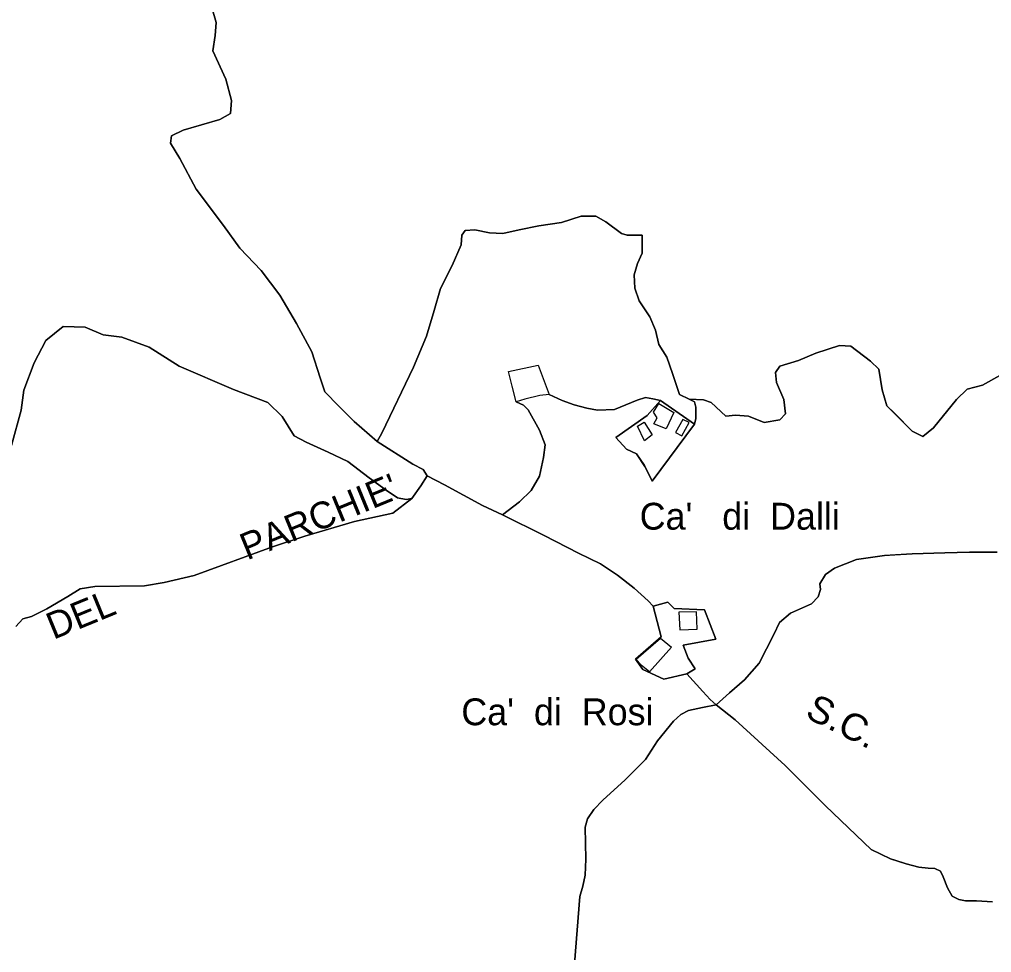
# Model space of a CAD drawing. Extents: x 645880 to 658994, y 884400 to 894744.
# Drawn here: x 653285 to 653901, y 891100 to 891691 of the extents above; entities that cross this region are included whole.
import ezdxf
from ezdxf.enums import TextEntityAlignment as Align

# ---------------------------------------------------------------- set-up
doc = ezdxf.new("R2010")
doc.units = 0
doc.header["$LTSCALE"] = 10
for name, color, linetype, lineweight in [('16', 7, 'Continuous', 25), ('18', 7, 'Continuous', 25), ('3', 7, 'Continuous', 25), ('4', 7, 'Continuous', 25)]:
    doc.layers.add(name, color=color, linetype=linetype, lineweight=lineweight)
doc.layers.add('60', color=7, linetype='Continuous')

msp = doc.modelspace()

# ---------------------------------------------------------------- linework, layer by layer
at = {"layer": '16'}
for points in [[(653982.6, 891577.12), (653973.26, 891579.64), (653963.41, 891578.13), (653958.74, 891573.6), (653953.56, 891554.48), (653953.56, 891524.3), (653953.04, 891499.64), (653949.93, 891489.58), (653943.19, 891484.55), (653929.78, 891480.64), (653921.48, 891475.61), (653906.44, 891465.54), (653895.55, 891459.51), (653885.7, 891456.99), (653878.96, 891450.45), (653864.44, 891432.34), (653857.7, 891426.8), (653850.96, 891430.32), (653839.8, 891441.5), (653839.8, 891441.51)], [(653712.85, 891434.77), (653713.65, 891438.39), (653713.86, 891445.39), (653712.99, 891448.89), (653709.6, 891450.58), (653703.38, 891453.57), (653698.9, 891466.76), (653695.38, 891477.12), (653690.2, 891485.17), (653688.12, 891494.22), (653684.49, 891502.78), (653677.75, 891512.84), (653675.16, 891520.89), (653674.64, 891529.44), (653676.72, 891536.49), (653679.83, 891543.03), (653679.83, 891554.6), (653670.17, 891554.46), (653666.54, 891555.47), (653656.69, 891563.02), (653650.46, 891566.54), (653641.13, 891566.54), (653628.68, 891562.51), (653614.16, 891560.5), (653601.72, 891557.98), (653591.35, 891555.47), (653583.05, 891555.97), (653573.72, 891557.98), (653567.49, 891557.48), (653565.42, 891554.46), (653564.9, 891548.42), (653559.2, 891535.34), (653551.94, 891520.75), (653547.79, 891506.66), (653543.12, 891490.56), (653534.82, 891470.94), (653514.63, 891428.94), (653511.76, 891423.65), (653534.38, 891409.3)], [(653282.78, 891306.52), (653287.22, 891311.4), (653292.53, 891312.73), (653302.29, 891317.61), (653315.58, 891325.59), (653323.56, 891330.47), (653332.87, 891331.8), (653364.34, 891332.24), (653376.75, 891334.46), (653395.81, 891338.9), (653445.45, 891357.08), (653465.84, 891363.73), (653497.31, 891373.04), (653521.69, 891378.36), (653533.65, 891387.68), (653530.21, 891386.92), (653524.55, 891388.08), (653517.52, 891392.8), (653506.71, 891400.67), (653493.19, 891411.16), (653480.76, 891416.93), (653466.7, 891423.22), (653459.13, 891427.42), (653451.57, 891439.48), (653442.38, 891448.4), (653420.75, 891456.79), (653386.15, 891471.47), (653367.23, 891483.53), (653349.93, 891489.83), (653338.03, 891491.4), (653326.68, 891496.12), (653312.62, 891496.64), (653301.81, 891487.73), (653294.24, 891473.57), (653287.75, 891456.26), (653286.13, 891443.68), (653279.91, 891421.22)], [(653839.8, 891441.51), (653834.88, 891446.43), (653831.77, 891456.49), (653829.69, 891469.57), (653824.51, 891474.6), (653812.06, 891484.16), (653804.8, 891484.66), (653789.76, 891479.63), (653778.87, 891475.1), (653766.95, 891471.58), (653764.35, 891467.56), (653764.87, 891461.02), (653769.54, 891450.45), (653770.53, 891441.37), (653766.95, 891437.37), (653757.09, 891435.86), (653747.24, 891439.88), (653738.94, 891440.39), (653732.72, 891439.88), (653723.39, 891448.44), (653718.55, 891450.08), (653709.6, 891450.58)], [(653554.39, 891396.26), (653578.51, 891383.22), (653591.21, 891377.35), (653601.97, 891385.5), (653609.46, 891392.68), (653614.68, 891401.81), (653617.29, 891413.55), (653618.26, 891421.7), (653614.63, 891430.96), (653607.51, 891443.87), (653604.58, 891446.81), (653599.78, 891448.86), (653597.29, 891458.87), (653594.95, 891468.17), (653613.91, 891472.07), (653620.83, 891453.6)], [(653691.31, 891449.65), (653686.47, 891450.84), (653681.86, 891451.64), (653676.66, 891449.84), (653662.24, 891444.03), (653651.43, 891443.63), (653644.63, 891444.83), (653636.62, 891447.04), (653629.01, 891449.64), (653620.83, 891453.6), (653614.83, 891452.8), (653605.42, 891450.6), (653599.78, 891448.86)], [(653620.83, 891453.6), (653629.01, 891449.64), (653636.62, 891447.04), (653644.63, 891444.83), (653651.43, 891443.63), (653662.24, 891444.03), (653676.66, 891449.84), (653681.86, 891451.64), (653686.47, 891450.84), (653691.31, 891449.65), (653712.85, 891434.77)], [(653709.6, 891450.58), (653712.99, 891448.89), (653713.86, 891445.39), (653713.65, 891438.39), (653712.85, 891434.77), (653686.09, 891398.67), (653681.46, 891407.83), (653676.19, 891415.97), (653669.89, 891418.97), (653662.98, 891426.33), (653683, 891440.16), (653691.31, 891449.65)], [(653599.78, 891448.86), (653604.58, 891446.81), (653607.51, 891443.87), (653614.63, 891430.96), (653618.26, 891421.7), (653617.29, 891413.55), (653614.68, 891401.81), (653609.46, 891392.68), (653601.97, 891385.5), (653591.21, 891377.35)], [(653534.38, 891409.3), (653540.91, 891405.97), (653543.41, 891402.07), (653554.39, 891396.26)], [(653591.21, 891377.35), (653578.51, 891383.22), (653554.39, 891396.26), (653543.41, 891402.07), (653539.38, 891395.54), (653533.65, 891387.68)], [(653533.65, 891387.68), (653521.69, 891378.36), (653497.31, 891373.04), (653465.84, 891363.73), (653445.45, 891357.08), (653395.81, 891338.9), (653376.75, 891334.46), (653364.34, 891332.24), (653332.87, 891331.8), (653323.56, 891330.47), (653315.58, 891325.59), (653302.29, 891317.61), (653292.53, 891312.73), (653287.22, 891311.4), (653282.78, 891306.52)], [(653686.64, 891319.48), (653683.63, 891322.8), (653674.69, 891330.89), (653664.06, 891338.98), (653653.42, 891346.22), (653639.38, 891353.03), (653617.67, 891364.1), (653591.21, 891377.35)], [(653591.21, 891377.35), (653617.67, 891364.1), (653639.38, 891353.03), (653653.42, 891346.22), (653664.06, 891338.98)], [(653718.1, 891265.32), (653722.78, 891260.21), (653726.72, 891256.83), (653735.02, 891264.44), (653744.53, 891272.79), (653753.87, 891283.36), (653763.2, 891301.47), (653766.83, 891309.02), (653773.67, 891314.84), (653781.45, 891318.36), (653787.15, 891320.88), (653791.3, 891325.4), (653792.86, 891329.93), (653792.34, 891333.45), (653795.97, 891339.49), (653801.67, 891343.52), (653815.68, 891349.05), (653833.31, 891351.57), (653839.8, 891351.94), (653850.94, 891352.57), (653871.68, 891353.08), (653887.24, 891353.58), (653904.87, 891353.58)], [(653664.06, 891338.98), (653674.69, 891330.89), (653683.63, 891322.8), (653686.64, 891319.48)], [(653686.64, 891319.48), (653696.05, 891321.84), (653699.96, 891317.92), (653719.18, 891317.1), (653726.35, 891298.57), (653705.69, 891294.67), (653708.89, 891286.43), (653713.3, 891279.66), (653707.96, 891276.59), (653718.1, 891265.32)], [(653726.72, 891256.83), (653722.78, 891260.21), (653718.1, 891265.32), (653707.96, 891276.59), (653693.57, 891273.16), (653680.08, 891279.34), (653675.41, 891285.76), (653691.87, 891299.88), (653686.64, 891319.48)], [(653619.68, 891027.76), (653624.41, 891037.97), (653629.84, 891059.69), (653633.37, 891070.27), (653636.89, 891092.8), (653640.15, 891135.42), (653642.05, 891141.93), (653643.67, 891148.99), (653643.95, 891159.03), (653643.67, 891179.39), (653645.03, 891184.55), (653649.1, 891190.52), (653654.8, 891196.49), (653668.91, 891209.25), (653681.93, 891222.28), (653689.52, 891233.95), (653699.56, 891246.44), (653704.17, 891250.78), (653709.06, 891253.23), (653718.01, 891255.13), (653726.72, 891256.83)], [(653726.72, 891256.83), (653718.01, 891255.13), (653709.06, 891253.23), (653704.17, 891250.78), (653699.56, 891246.44), (653689.52, 891233.95), (653681.93, 891222.28), (653668.91, 891209.25), (653654.8, 891196.49), (653649.1, 891190.52), (653645.03, 891184.55), (653643.67, 891179.39), (653643.95, 891159.03), (653643.67, 891148.99), (653642.05, 891141.93), (653640.15, 891135.42), (653636.89, 891092.8), (653633.37, 891070.27), (653629.84, 891059.69), (653624.41, 891037.97), (653619.68, 891027.76), (653636.37, 891015.55)], [(653839.8, 891158.4), (653837.14, 891159.19), (653824.83, 891165.18), (653795.91, 891192.82), (653770.28, 891218.48), (653738.73, 891247.44), (653726.72, 891256.83)], [(653901.81, 891131.94), (653891.76, 891132.69), (653884.8, 891132.69), (653880.42, 891133.44), (653876.3, 891135.69), (653873.21, 891140.94), (653870.63, 891147.94), (653868.83, 891151.44), (653865.22, 891153.19), (653861.1, 891153.44), (653855.18, 891153.94), (653847.19, 891156.19), (653839.8, 891158.4)]]:
    msp.add_lwpolyline(points, dxfattribs=at)
at = {"layer": '18'}
for points in [[(653511.76, 891423.65), (653497.21, 891436.44), (653487.5, 891446.16), (653478.53, 891455.13), (653475.54, 891464.1), (653470.31, 891480.55), (653460.6, 891498.5), (653450.14, 891516.44), (653438.18, 891532.15), (653424.73, 891546.35), (653414.27, 891560.56), (653397.09, 891583.74), (653386.63, 891603.18), (653380.65, 891612.9), (653381.4, 891617.39), (653388.87, 891621.12), (653412.03, 891627.85), (653418.76, 891631.59), (653419.5, 891639.82), (653415.77, 891653.28), (653407.55, 891671.22), (653409.04, 891680.94), (653409.79, 891689.17), (653407.03, 891698.75)], [(653407.03, 891698.75), (653409.79, 891689.17), (653409.04, 891680.94), (653407.55, 891671.22), (653415.77, 891653.28), (653419.5, 891639.82), (653418.76, 891631.59), (653412.03, 891627.85), (653388.87, 891621.12), (653381.4, 891617.39), (653380.65, 891612.9), (653386.63, 891603.18), (653397.09, 891583.74), (653414.27, 891560.56), (653424.73, 891546.35), (653438.18, 891532.15), (653450.14, 891516.44), (653460.6, 891498.5), (653470.31, 891480.55), (653475.54, 891464.1), (653478.53, 891455.13), (653487.5, 891446.16), (653497.21, 891436.44), (653511.76, 891423.65), (653514.63, 891428.94), (653534.82, 891470.94), (653543.12, 891490.56), (653547.79, 891506.66), (653551.94, 891520.75), (653559.2, 891535.34), (653564.9, 891548.42), (653565.42, 891554.46), (653567.49, 891557.48), (653573.72, 891557.98), (653583.05, 891555.97), (653591.35, 891555.47), (653601.72, 891557.98), (653614.16, 891560.5), (653628.68, 891562.51), (653641.13, 891566.54)], [(653641.13, 891566.54), (653650.46, 891566.54), (653656.69, 891563.02), (653666.54, 891555.47), (653670.17, 891554.46), (653679.83, 891554.6), (653679.83, 891543.03), (653676.72, 891536.49), (653674.64, 891529.44), (653675.16, 891520.89), (653677.75, 891512.84), (653684.49, 891502.78), (653688.12, 891494.22), (653690.2, 891485.17), (653695.38, 891477.12), (653698.9, 891466.76), (653703.38, 891453.57), (653709.6, 891450.58), (653718.55, 891450.08), (653723.39, 891448.44), (653732.72, 891439.88), (653738.94, 891440.39), (653747.24, 891439.88), (653757.09, 891435.86), (653766.95, 891437.37), (653770.53, 891441.37), (653769.54, 891450.45), (653764.87, 891461.02), (653764.35, 891467.56), (653766.95, 891471.58), (653778.87, 891475.1), (653789.76, 891479.63), (653804.8, 891484.66), (653812.06, 891484.16), (653824.51, 891474.6), (653829.69, 891469.57), (653831.77, 891456.49), (653834.88, 891446.43), (653850.96, 891430.32), (653857.7, 891426.8)], [(653279.91, 891421.22), (653286.13, 891443.68), (653287.75, 891456.26), (653294.24, 891473.57), (653301.81, 891487.73), (653312.62, 891496.64), (653326.68, 891496.12), (653338.03, 891491.4), (653349.93, 891489.83), (653367.23, 891483.53), (653386.15, 891471.47), (653420.75, 891456.79), (653442.38, 891448.4), (653451.57, 891439.48), (653459.13, 891427.42)], [(653857.7, 891426.8), (653864.44, 891432.34), (653878.96, 891450.45), (653885.7, 891456.99), (653895.55, 891459.51), (653906.44, 891465.54)], [(653459.13, 891427.42), (653466.7, 891423.22), (653480.76, 891416.93), (653493.19, 891411.16), (653506.71, 891400.67), (653517.52, 891392.8), (653524.55, 891388.08), (653530.21, 891386.93), (653533.65, 891387.68), (653539.37, 891395.54), (653543.4, 891402.08), (653540.9, 891405.97), (653534.37, 891409.3), (653511.76, 891423.65)], [(653904.87, 891353.58), (653887.24, 891353.58), (653871.68, 891353.08), (653850.94, 891352.57), (653833.31, 891351.57), (653815.68, 891349.05), (653801.67, 891343.52)], [(653801.67, 891343.52), (653795.97, 891339.49), (653792.34, 891333.45), (653792.86, 891329.93), (653791.3, 891325.4), (653787.15, 891320.88), (653781.45, 891318.36), (653773.67, 891314.84), (653766.83, 891309.02), (653763.2, 891301.47), (653753.87, 891283.36), (653744.53, 891272.79), (653735.02, 891264.44), (653726.72, 891256.83), (653738.73, 891247.44), (653770.28, 891218.48), (653795.91, 891192.82), (653824.83, 891165.18), (653837.14, 891159.19), (653847.19, 891156.19), (653855.18, 891153.94), (653861.1, 891153.44), (653865.22, 891153.19), (653868.83, 891151.44), (653870.63, 891147.94), (653873.21, 891140.94), (653876.3, 891135.69), (653880.42, 891133.44), (653884.8, 891132.69), (653891.76, 891132.69), (653901.81, 891131.94)]]:
    msp.add_lwpolyline(points, dxfattribs=at)
at = {"layer": '3'}
for points in [[(653699.96, 891317.92), (653696.05, 891321.84), (653686.64, 891319.48)], [(653686.64, 891319.48), (653691.87, 891299.88), (653675.41, 891285.76), (653680.08, 891279.34), (653693.57, 891273.16), (653707.96, 891276.59), (653713.3, 891279.66), (653708.89, 891286.43), (653705.69, 891294.67), (653726.35, 891298.57), (653719.18, 891317.1), (653699.96, 891317.92)]]:
    msp.add_lwpolyline(points, dxfattribs=at)
for points in [[(653703.01, 891315.59), (653703.62, 891304.39), (653714.6, 891304.9), (653714.08, 891315.81)], [(653691.35, 891299.09), (653698.4, 891293.34), (653684.33, 891277.77), (653679.01, 891282.06), (653676.02, 891285.83)]]:
    msp.add_lwpolyline(points, close=True, dxfattribs=at)
at = {"layer": '4'}
for points in [[(653605.42, 891450.6), (653599.78, 891448.86), (653597.29, 891458.87), (653594.95, 891468.17), (653613.91, 891472.07), (653620.83, 891453.6), (653614.83, 891452.8)], [(653676.19, 891415.97), (653681.28, 891408.6), (653686.09, 891398.67), (653712.85, 891434.77), (653691.31, 891449.65), (653683, 891440.16), (653662.98, 891426.33), (653669.89, 891418.97)], [(653686.87, 891442.38), (653690.26, 891447.89), (653699.74, 891442.15), (653694.94, 891431.72), (653687.22, 891434.88), (653689.21, 891438.63)], [(653705.48, 891437.7), (653700.91, 891429.5), (653704.78, 891427.39), (653709.46, 891435.82)], [(653681.01, 891435.94), (653686.05, 891427.86), (653681.13, 891424.22), (653676.68, 891433.36)]]:
    msp.add_lwpolyline(points, close=True, dxfattribs=at)

# ---------------------------------------------------------------- texts
at = {"layer": '60'}
msp.add_text("S.C.            DEL              PARCHIE'", height=17, rotation=22.275, dxfattribs=at).set_placement((653361.15, 891320.37), align=Align.CENTER)
for s, p in [("Ca'   di  Dalli", (653741.6, 891367.88)), ("Ca'  di  Rosi", (653626.01, 891243.93))]:
    msp.add_text(s, height=17, dxfattribs=at).set_placement(p, align=Align.CENTER)
at = {"layer": '60', "width": 1.05}
msp.add_text('S.C.', height=17, rotation=333.419, dxfattribs=at).set_placement((653803.05, 891238.9), align=Align.CENTER)

doc.saveas('drawing.dxf')
